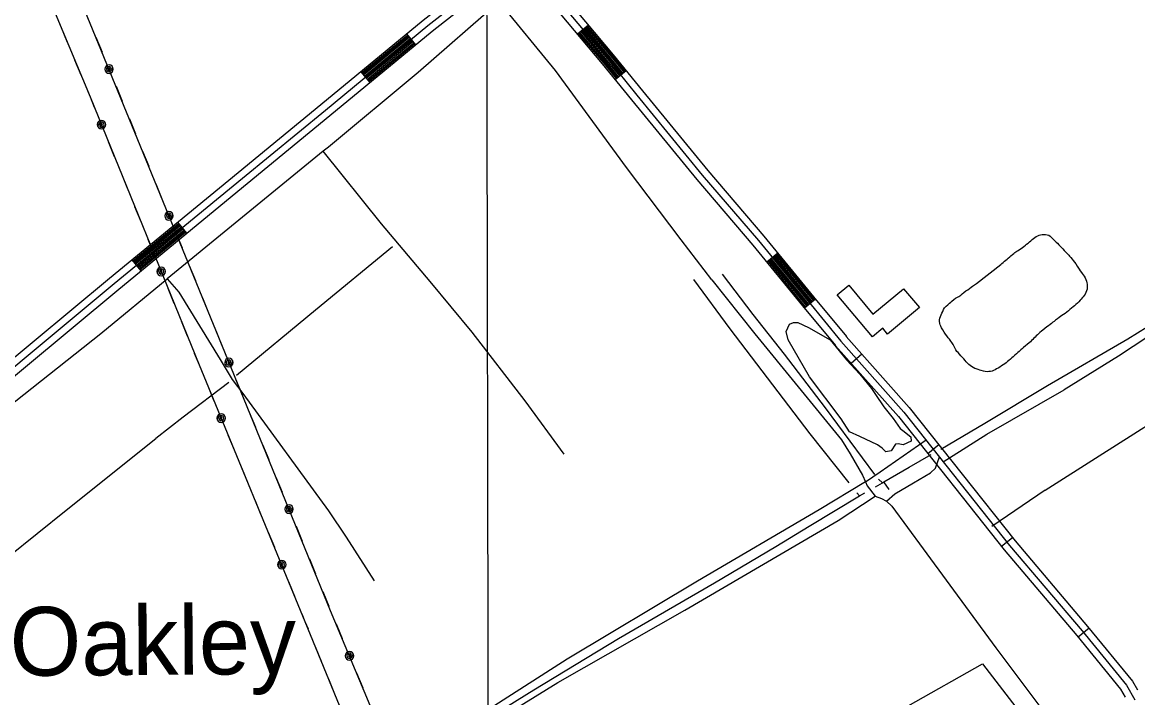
# Model space of a CAD drawing. Extents: x 3329332 to 3367211, y 631066 to 656469.
# Drawn here: x 3353510 to 3355862, y 642954 to 644377 of the extents above; entities that cross this region are included whole.
import ezdxf

# ---------------------------------------------------------------- set-up
doc = ezdxf.new("R2010")
doc.units = 0
for name, color, linetype in [('V-BLDG-OTLN', 7, 'Continuous'), ('V-DTCH-CNTR', 7, 'Continuous'), ('V-GRID-MAJR', 7, 'Continuous'), ('V-RIVR-JETY', 7, 'Continuous'), ('V-ROAD-CNTR', 7, 'Continuous'), ('V-TOPO-GNAM-IDEN', 7, 'Continuous'), ('V-TOPO-SHOR', 7, 'Continuous'), ('V-UTIL-LINE', 7, 'Continuous')]:
    doc.layers.add(name, color=color, linetype=linetype)

msp = doc.modelspace()

# ---------------------------------------------------------------- linework, layer by layer
at = {"layer": 'V-BLDG-OTLN'}
msp.add_lwpolyline([(3355401.4, 643776.5), (3355334.5, 643720.5), (3355324, 643733), (3355302.4, 643714.9), (3355228.3, 643803.3), (3355252.3, 643823.4), (3355303.4, 643762.3), (3355367.6, 643816)], close=True, dxfattribs=at)
at = {"layer": 'V-DTCH-CNTR'}
msp.add_line((3355666.5, 643391.5), (3355554.1, 643315), dxfattribs=at)
for points in [[(3354964.1, 643834.5), (3354899.2, 643919.1), (3354783.6, 644071.4), (3354633.9, 644275.9), (3354515.7, 644420.6), (3354344.4, 644271.6), (3354155.7, 644114.5), (3354144.7, 644105.6), (3353958.7, 643953.8), (3353815.2, 643837), (3353840.1, 643808.4)], [(3354369.6, 643831.2), (3354267, 643952.7), (3354144.7, 644105.6)], [(3353305.7, 643437.1), (3353458.6, 643550.1), (3353675.6, 643721.3), (3353815.2, 643837)], [(3354652.7, 643467.6), (3354570, 643579.4), (3354458.2, 643724.4), (3354369.6, 643831.2)], [(3354964.1, 643834.5), (3355054.2, 643721.2), (3355237.2, 643497.4), (3355255.3, 643468), (3355281.3, 643423.1), (3355287.7, 643408.8), (3355291.4, 643400.4), (3355308.1, 643379), (3355321.3, 643373.8), (3355332.2, 643368.6), (3355343.1, 643357.5), (3355409.2, 643267.8), (3355562.3, 643059.5), (3355676.2, 642907.2)], [(3353840.1, 643808.4), (3353927, 643666.5), (3353952.3, 643624.6), (3353974.8, 643595.1), (3354155.5, 643347.9), (3354192.5, 643292.8), (3354251.9, 643200.1)], [(3355666.5, 643391.5), (3355780.1, 643464.1), (3355970.6, 643584.8), (3356029.1, 643619), (3355942.8, 643754.1), (3355821.4, 643673.9), (3355706.4, 643602.9)], [(3355451.4, 643451.4), (3355543.4, 643509.3), (3355706.4, 643602.9)], [(3355287.7, 643408.8), (3355318.6, 643430.1), (3355415.4, 643497.3)], [(3355332.2, 643368.6), (3355349.9, 643383.9), (3355388.9, 643407), (3355424.9, 643428), (3355435.2, 643438.2), (3355443.8, 643461.8)], [(3355287.7, 643408.8), (3355190.3, 643350.2), (3354933.8, 643199.5), (3354658.7, 643035.1), (3354478.6, 642920.1), (3354273, 642789), (3354003.3, 642630.8), (3353935.2, 642590), (3353707.7, 642453.7)], [(3353957.6, 642557.2), (3354113.8, 642657), (3354391.3, 642832.9), (3354639.4, 642986), (3354906.7, 643138.9), (3355230.5, 643327.6), (3355308.1, 643379)]]:
    msp.add_lwpolyline(points, dxfattribs=at)
at = {"layer": 'V-GRID-MAJR'}
msp.add_spline([(3354505.6, 636487.8), (3354493.2, 642546.1), (3354480.9, 648607.4), (3354468.6, 654668.8), (3354468.6, 654671.8)], degree=3, dxfattribs=at)
at = {"layer": 'V-RIVR-JETY'}
msp.add_lwpolyline([(3355384, 643495), (3355367.5, 643487.2), (3355356.9, 643489.2), (3355351, 643488.5), (3355341.8, 643474.4), (3355330.4, 643472.1), (3355322.6, 643480.1), (3355312.9, 643486.8), (3355275.7, 643504.7), (3355254.1, 643514.7), (3355236.6, 643541.5), (3355169.6, 643630.4), (3355124.6, 643708), (3355120.8, 643726.1), (3355127.6, 643741.4), (3355136.2, 643744.9), (3355145.3, 643744.8), (3355167.6, 643734.5), (3355213, 643708.6), (3355247.7, 643666), (3355275.7, 643635.9), (3355300.7, 643605.9), (3355308.9, 643593.3), (3355326.4, 643566.8), (3355346.2, 643542.7), (3355360.6, 643521.4), (3355366.5, 643517.1), (3355383.7, 643503.6), (3355384, 643495)], dxfattribs=at)
at = {"layer": 'V-ROAD-CNTR'}
for p, q in [((3354703.5, 644371.5), (3354680.5, 644352.2)), ((3354320, 644352.9), (3354339.1, 644329.8)), ((3354783.5, 644275.1), (3354760.2, 644256.2)), ((3354223.6, 644273.3), (3354242.7, 644250.2)), ((3353837.3, 643956), (3353856.3, 643932.8)), ((3353740.7, 643876.7), (3353759.7, 643853.5)), ((3355103.1, 643890.8), (3355079.9, 643871.7)), ((3355182.4, 643794.1), (3355159.3, 643775.1)), ((3355280.3, 643678.2), (3355257.8, 643658.3)), ((3355442.5, 643487), (3355419, 643468.4)), ((3355597.8, 643291.2), (3355574.3, 643272.5)), ((3355759.2, 643100.6), (3355736, 643081.6))]:
    msp.add_line(p, q, dxfattribs=at)
for points in [[(3353218.9, 643449.7), (3353296.3, 643507.8), (3353694.1, 643838.5), (3353964.8, 644060.6), (3354139.5, 644203.9), (3354355.5, 644382.2), (3354528.4, 644517.8)], [(3353227.9, 643437.7), (3353305.6, 643496.1), (3353703.7, 643826.9), (3353974.3, 644049), (3354149, 644192.4), (3354364.9, 644370.5), (3354558, 644521.9), (3354744.4, 644299.4), (3354805.8, 644223.8), (3354943.7, 644055.6), (3355061.9, 643917.3), (3355166.7, 643789.7), (3355235.9, 643705.7)], [(3354577.3, 644522.2), (3354755.9, 644308.9), (3354817.4, 644233.3), (3354955.2, 644065.2), (3355073.4, 643927), (3355178.3, 643799.2), (3355247.4, 643715.2)], [(3353236.9, 643425.7), (3353314.9, 643484.3), (3353713.2, 643815.4), (3353983.8, 644037.4), (3354158.5, 644180.8), (3354374.3, 644358.8), (3354555.8, 644501.2), (3354732.8, 644289.9), (3354794.2, 644214.3), (3354932.2, 644046), (3355050.4, 643907.7), (3355155.1, 643780.1), (3355224.3, 643696.1)], [(3354701.2, 644369.6), (3354753.6, 644307), (3354781.1, 644273.2)], [(3354225.5, 644271), (3354321.9, 644350.6)], [(3354227.4, 644268.7), (3354323.8, 644348.3)], [(3354229.3, 644266.4), (3354325.7, 644346)], [(3354682.8, 644354.1), (3354735.1, 644291.8), (3354762.5, 644258)], [(3354685.1, 644356.1), (3354737.4, 644293.7), (3354764.8, 644259.9)], [(3354687.4, 644358), (3354739.7, 644295.6), (3354767.2, 644261.8)], [(3354689.7, 644359.9), (3354742, 644297.5), (3354769.5, 644263.7)], [(3354692, 644361.9), (3354744.4, 644299.4), (3354771.8, 644265.6)], [(3354694.3, 644363.8), (3354746.7, 644301.3), (3354774.1, 644267.5)], [(3354696.6, 644365.7), (3354749, 644303.2), (3354776.5, 644269.4)], [(3354698.9, 644367.6), (3354751.3, 644305.1), (3354778.8, 644271.3)], [(3354231.2, 644264.1), (3354327.7, 644343.6)], [(3354233.1, 644261.8), (3354329.6, 644341.3)], [(3354235.1, 644259.5), (3354331.5, 644339)], [(3354237, 644257.1), (3354333.4, 644336.7)], [(3354238.9, 644254.8), (3354335.3, 644334.4)], [(3354240.8, 644252.5), (3354337.2, 644332.1)], [(3353742.6, 643874.3), (3353839.2, 643953.6)], [(3353744.5, 643872), (3353841.1, 643951.3)], [(3353746.4, 643869.7), (3353843, 643949)], [(3353748.3, 643867.4), (3353844.9, 643946.7)], [(3353750.2, 643865.1), (3353846.8, 643944.4)], [(3353752.1, 643862.7), (3353848.7, 643942)], [(3353754, 643860.4), (3353850.6, 643939.7)], [(3353755.9, 643858.1), (3353852.5, 643937.4)], [(3353757.8, 643855.8), (3353854.4, 643935.1)], [(3355084.6, 643875.5), (3355159.7, 643784), (3355163.9, 643778.9)], [(3355086.9, 643877.4), (3355162, 643785.9), (3355166.2, 643780.8)], [(3355089.2, 643879.3), (3355164.3, 643787.8), (3355168.5, 643782.7)], [(3355091.5, 643881.2), (3355166.7, 643789.7), (3355170.8, 643784.6)], [(3355093.9, 643883.1), (3355169, 643791.6), (3355173.1, 643786.5)], [(3355096.2, 643885), (3355171.3, 643793.5), (3355175.5, 643788.4)], [(3355098.5, 643886.9), (3355173.6, 643795.4), (3355177.8, 643790.3)], [(3355100.8, 643888.9), (3355175.9, 643797.3), (3355180.1, 643792.2)], [(3355082.3, 643873.6), (3355157.4, 643782), (3355161.6, 643777)], [(3355247.1, 643715.6), (3355380.1, 643565.6), (3355603, 643284.6), (3355756.1, 643104.5), (3355850.4, 642989.3), (3355861.1, 642970.5)], [(3355224.6, 643695.7), (3355357.1, 643546.4), (3355579.9, 643265.5), (3355733, 643085.2), (3355825.6, 642972.2), (3355835.2, 642955.3)], [(3355235.9, 643705.7), (3355368.6, 643556), (3355591.4, 643275.1), (3355744.5, 643094.8), (3355838, 642980.7), (3355855.7, 642949.7)]]:
    msp.add_lwpolyline(points, dxfattribs=at)
at = {"layer": 'V-TOPO-SHOR'}
for p, q in [((3355315, 643415), (3355323.4, 643406.9)), ((3355337.8, 643392.6), (3355326.7, 643408.8)), ((3355269.3, 643385.6), (3355275.1, 643379.4))]:
    msp.add_line(p, q, dxfattribs=at)
for points in [[(3355573, 643866.8), (3355575.3, 643869), (3355577.7, 643871.4), (3355580.6, 643873.9), (3355583.5, 643876.4), (3355586.2, 643878.4), (3355588.8, 643880.4), (3355592.2, 643883.4), (3355594.5, 643885.6), (3355597.4, 643887.9), (3355600.2, 643890.3), (3355602.6, 643892.2), (3355606.8, 643895), (3355609.5, 643896.6), (3355612.8, 643898.7), (3355616, 643900.8), (3355618.5, 643902.9), (3355621.7, 643905.3), (3355624.8, 643907.5), (3355627.4, 643909.6), (3355630.5, 643912.3), (3355633.6, 643914.8), (3355636.4, 643917.1), (3355639.2, 643919.4), (3355642.3, 643922), (3355644.8, 643923.8), (3355647.8, 643925.8), (3355650.8, 643927.3), (3355653.7, 643928.5), (3355656.9, 643929.3), (3355660.4, 643929.9), (3355664.1, 643930.4), (3355667.4, 643930.4), (3355670.8, 643929.8), (3355674.4, 643928.6), (3355677.1, 643926.5), (3355679.7, 643924.1), (3355681.9, 643922), (3355685, 643919.1), (3355687.2, 643916.9), (3355689.7, 643914.4), (3355692.3, 643911.7), (3355695.3, 643908.6), (3355698.5, 643905.4), (3355700.7, 643903.2), (3355703.9, 643899.7), (3355706.9, 643896.4), (3355710.3, 643892.8), (3355712.8, 643890.3), (3355716.2, 643886.8), (3355718.2, 643884.4), (3355720.8, 643881.5), (3355723.5, 643878.3), (3355725.8, 643875.4), (3355728.4, 643871.7), (3355731, 643868.2), (3355733.8, 643863.8), (3355735.8, 643861.1), (3355738.3, 643857.5), (3355740.6, 643853.9), (3355743, 643850.4), (3355744.8, 643847.9), (3355746.8, 643845), (3355748.7, 643842.6), (3355750.9, 643838.8), (3355752.5, 643835.2), (3355753.7, 643831.8), (3355754.4, 643828.6), (3355755, 643825.4), (3355755.3, 643821.4), (3355755.2, 643818.3), (3355754.8, 643815.1), (3355753.5, 643811.2), (3355752.4, 643808.2), (3355750.7, 643804.7), (3355749, 643801.8), (3355746.8, 643798.8), (3355744.8, 643796.5), (3355742.7, 643794.3), (3355740.3, 643791.7), (3355737.7, 643788.7), (3355734.9, 643785.9), (3355731.4, 643782.6), (3355728.5, 643780.2), (3355725.6, 643777.9), (3355722.2, 643775), (3355718.6, 643772), (3355715.7, 643769.7), (3355712, 643766.8), (3355708.4, 643764), (3355705.4, 643761.8), (3355701.9, 643759.4), (3355698.6, 643757.2), (3355695.9, 643755.4), (3355692.4, 643752.8), (3355688.6, 643749.7), (3355685.3, 643747.1), (3355683, 643745.3), (3355679.8, 643742.8), (3355677.4, 643740.9), (3355673.3, 643737.8)], [(3354290.7, 643904.6), (3354128.3, 643770.8), (3353961.6, 643633.4)], [(3355503.2, 643814), (3355507.1, 643816.8), (3355510.8, 643819.6), (3355513.6, 643821.7), (3355517.3, 643824.4), (3355522.1, 643827.2), (3355573, 643866.8)], [(3355253.2, 643406.9), (3355170.8, 643510.4), (3355002.3, 643731.8), (3354926, 643835.2)], [(3354985.6, 643847), (3355050.5, 643762), (3355116.3, 643678.4), (3355202.5, 643565), (3355306.7, 643424.8)], [(3355673.3, 643737.8), (3355669.9, 643735.4), (3355665.8, 643732.1), (3355661.8, 643729), (3355658.8, 643726.6), (3355655.6, 643723.9), (3355652.9, 643721.7), (3355650.5, 643719.1), (3355647.8, 643716.4), (3355645.3, 643714), (3355643, 643711.7), (3355640.5, 643709.3), (3355637.7, 643706.8), (3355635.4, 643704.4), (3355632.6, 643701.9), (3355628.7, 643698.4), (3355625.1, 643695.3), (3355621.2, 643692), (3355618.6, 643689.8), (3355615.2, 643687), (3355611.9, 643684), (3355609.2, 643681.5), (3355605.9, 643678.6), (3355602.9, 643675.9), (3355599.1, 643672.6), (3355596.4, 643670.1), (3355593.5, 643667.8), (3355589.8, 643664.5), (3355587.3, 643662.4), (3355584.2, 643660), (3355581.3, 643657.7), (3355577.9, 643655.3), (3355574.5, 643653.2), (3355571, 643650.8), (3355567.7, 643648.9), (3355564.3, 643647.2), (3355560.9, 643645.1), (3355557.9, 643643.5), (3355554.8, 643642.3), (3355551.4, 643641.5), (3355547.7, 643641.4), (3355544.1, 643641), (3355540.2, 643641.4), (3355536.7, 643642.3), (3355531.7, 643643.7), (3355528.8, 643644.4), (3355525.1, 643645.7), (3355521.3, 643646.9), (3355518.2, 643648), (3355514.5, 643650), (3355511, 643652), (3355508.5, 643653.9), (3355505.8, 643656.4), (3355502.9, 643659.2), (3355500, 643661.9), (3355498, 643664.5), (3355494.9, 643668.2), (3355491.6, 643671.9), (3355489, 643674.6), (3355486, 643677.9), (3355482.9, 643681.3), (3355480.6, 643683.9), (3355478.5, 643687.1), (3355475.9, 643691.7), (3355473.8, 643695.7), (3355472.3, 643698.4), (3355469.9, 643702.5), (3355467.6, 643705.8), (3355464.8, 643709.4), (3355462.4, 643712.4), (3355459.5, 643716.5), (3355456.6, 643720.4), (3355453.6, 643724.7), (3355451, 643729.2), (3355448.3, 643733.9), (3355446.9, 643736.8), (3355445.3, 643740), (3355444.4, 643742.9), (3355443.7, 643747.5), (3355443.5, 643750.6), (3355444.2, 643753.7), (3355445.9, 643757.6), (3355447.4, 643761.3), (3355449, 643764.6), (3355450.5, 643768.3), (3355452.5, 643772.3), (3355454.6, 643775.8), (3355457.7, 643779), (3355461.3, 643782.2), (3355464.9, 643785.4), (3355467.5, 643787.8), (3355470.1, 643790), (3355473.7, 643793.1), (3355477.3, 643795.8), (3355480.5, 643797.6), (3355484.5, 643799.9), (3355488.6, 643802.6), (3355491.5, 643805), (3355495.1, 643807.9), (3355499.6, 643811.4), (3355503.2, 643814)], [(3355671.4, 643612.4), (3355841, 643710.4), (3355942.7, 643773.6)], [(3353945.5, 643618.2), (3353849.4, 643545.4), (3353791.3, 643500.7)], [(3355446.4, 643478.2), (3355539.7, 643532.4), (3355671.4, 643612.4)], [(3353414, 643199.1), (3353480, 643251.1), (3353602.6, 643349.1), (3353791.3, 643500.7)], [(3355308.6, 643398.3), (3355323.4, 643406.9), (3355326.7, 643408.8), (3355379.8, 643439.7), (3355426.5, 643466.9)], [(3353958.4, 642575.6), (3354053.3, 642635.2), (3354196.4, 642725), (3354396.3, 642851), (3354588.4, 642970.9), (3354766.7, 643078.7), (3354969.5, 643196.3), (3355098.9, 643273.1), (3355169.3, 643315.4), (3355275.1, 643379.4), (3355286.4, 643386.2)], [(3355249.6, 642854.4), (3355377.8, 642937), (3355534.5, 643025.7), (3355668.3, 642852.1)]]:
    msp.add_lwpolyline(points, dxfattribs=at)
at = {"layer": 'V-UTIL-LINE'}
for points in [[(3355057, 640957.9), (3354832.9, 641498.1), (3354614.4, 642039.4), (3354397.9, 642569), (3354160.1, 643137.5), (3353936.7, 643682.3), (3353706.1, 644246.6), (3353477.2, 644804.1), (3353249.1, 645361.4), (3353019.3, 645913.3), (3352822.6, 646394.7), (3352634.2, 646842.1), (3352469.8, 647270.3), (3352329.5, 647842.2)], [(3354997, 640934.2), (3354562.2, 642013.6), (3354336, 642554.4), (3354106.7, 643114.4), (3353883.4, 643654.7), (3353653.6, 644219.7), (3353419.4, 644779.3), (3353196.6, 645329.8), (3352962.2, 645897), (3352767.7, 646365.7), (3352563.9, 646828.2), (3352422, 647304), (3352297.4, 647805.2)], [(3353605.5, 644334.5), (3353592.4, 644365.9)], [(3353665.2, 644346.2), (3353678.1, 644314.8)], [(3353634.1, 644266.2), (3353621, 644297.6)], [(3353692.9, 644278.7), (3353694.5, 644281.1), (3353692.1, 644281), (3353690.7, 644278.7), (3353692.1, 644276.1), (3353695.3, 644277.3), (3353697.2, 644281.6), (3353694.1, 644284.5), (3353689.3, 644283.9), (3353687.3, 644279.8), (3353688.1, 644275.3), (3353692.3, 644273.1), (3353697.5, 644274.9), (3353701.2, 644282.1), (3353699.3, 644285.1), (3353696.4, 644287), (3353692.9, 644287.7), (3353689.5, 644287), (3353686.5, 644285.1), (3353684.6, 644282.2), (3353683.9, 644278.7), (3353684.6, 644275.3), (3353686.5, 644272.4), (3353689.4, 644270.4), (3353692.9, 644269.7), (3353696.3, 644270.4), (3353699.2, 644272.3), (3353701.2, 644275.2), (3353701.9, 644278.7), (3353701.2, 644282.1)], [(3353662.4, 644197.9), (3353653.6, 644219.7), (3353649.5, 644229.3)], [(3353707.7, 644242.6), (3353720.6, 644211.2)], [(3353677.1, 644161.8), (3353675.6, 644159.3), (3353677.9, 644159.4), (3353679.3, 644161.8), (3353677.9, 644164.3), (3353674.7, 644163.2), (3353672.8, 644158.9), (3353675.9, 644156), (3353680.7, 644156.6), (3353682.7, 644160.7), (3353682, 644165.1), (3353677.7, 644167.4), (3353672.5, 644165.6), (3353668.8, 644158.4), (3353670.7, 644155.4), (3353673.6, 644153.5), (3353677.1, 644152.8), (3353680.5, 644153.4), (3353683.5, 644155.4), (3353685.4, 644158.3), (3353686.1, 644161.7), (3353685.5, 644165.1), (3353683.5, 644168.1), (3353680.6, 644170.1), (3353677.2, 644170.8), (3353673.8, 644170.1), (3353670.8, 644168.2), (3353668.8, 644165.3), (3353668.1, 644161.8), (3353668.8, 644158.4)], [(3353735.7, 644174.1), (3353748.5, 644142.7)], [(3353704.6, 644094.1), (3353691.8, 644125.6)], [(3353763.7, 644105.6), (3353776.5, 644074.2)], [(3353732.5, 644025.6), (3353719.7, 644057.1)], [(3353791.7, 644037.1), (3353804.5, 644005.7)], [(3353760.4, 643957), (3353747.6, 643988.5)], [(3353819.3, 643969.6), (3353820.9, 643972), (3353818.5, 643971.9), (3353817.1, 643969.5), (3353818.5, 643967), (3353821.7, 643968.1), (3353823.6, 643972.4), (3353820.5, 643975.3), (3353815.7, 643974.7), (3353813.7, 643970.6), (3353814.4, 643966.2), (3353818.7, 643963.9), (3353823.9, 643965.7), (3353827.6, 643973), (3353825.7, 643975.9), (3353822.8, 643977.9), (3353819.3, 643978.6), (3353815.9, 643977.9), (3353813, 643975.9), (3353811, 643973), (3353810.3, 643969.6), (3353811, 643966.1), (3353812.9, 643963.2), (3353815.8, 643961.3), (3353819.2, 643960.6), (3353822.7, 643961.2), (3353825.6, 643963.2), (3353827.6, 643966.1), (3353828.3, 643969.5), (3353827.6, 643973)], [(3353834, 643933.5), (3353846.9, 643902)], [(3353788.3, 643888.5), (3353775.5, 643920)], [(3353803, 643852.4), (3353801.4, 643850), (3353803.7, 643850), (3353805.2, 643852.4), (3353803.8, 643854.9), (3353800.6, 643853.8), (3353798.7, 643849.5), (3353801.8, 643846.6), (3353806.6, 643847.2), (3353808.6, 643851.3), (3353807.8, 643855.7), (3353803.6, 643858), (3353798.4, 643856.2), (3353794.6, 643849), (3353796.6, 643846.1), (3353799.5, 643844.1), (3353802.9, 643843.4), (3353806.4, 643844), (3353809.3, 643846), (3353811.3, 643848.9), (3353812, 643852.3), (3353811.3, 643855.8), (3353809.4, 643858.7), (3353806.5, 643860.7), (3353803, 643861.4), (3353799.6, 643860.7), (3353796.7, 643858.8), (3353794.7, 643855.9), (3353794, 643852.4), (3353794.6, 643849)], [(3353862, 643865), (3353874.9, 643833.5)], [(3353830.5, 643784.8), (3353817.7, 643816.2)], [(3353890, 643796.5), (3353902.9, 643765)], [(3353858.4, 643716.2), (3353845.6, 643747.7)], [(3353918, 643728), (3353930.9, 643696.5)], [(3353886.3, 643647.7), (3353883.4, 643654.7), (3353873.4, 643679.2)], [(3353945.7, 643660.4), (3353947.2, 643662.8), (3353944.9, 643662.7), (3353943.5, 643660.4), (3353944.9, 643657.8), (3353948.1, 643658.9), (3353950, 643663.2), (3353946.9, 643666.1), (3353942, 643665.6), (3353940.1, 643661.4), (3353940.8, 643657), (3353945.1, 643654.8), (3353950.3, 643656.5), (3353954, 643663.8), (3353952.1, 643666.7), (3353949.1, 643668.7), (3353945.7, 643669.4), (3353942.2, 643668.7), (3353939.3, 643666.8), (3353937.4, 643663.9), (3353936.7, 643660.4), (3353937.3, 643657), (3353939.3, 643654), (3353942.2, 643652.1), (3353945.6, 643651.4), (3353949.1, 643652.1), (3353952, 643654), (3353954, 643656.9), (3353954.7, 643660.4), (3353954, 643663.8)], [(3353960.5, 643624.3), (3353973.4, 643592.8)], [(3353914.6, 643579.3), (3353901.6, 643610.7)], [(3353929.4, 643543.2), (3353927.9, 643540.8), (3353930.2, 643540.9), (3353931.6, 643543.3), (3353930.2, 643545.8), (3353927, 643544.7), (3353925.1, 643540.4), (3353928.3, 643537.5), (3353933.1, 643538.1), (3353935, 643542.2), (3353934.3, 643546.6), (3353930, 643548.9), (3353924.8, 643547.1), (3353921.1, 643539.8), (3353923.1, 643536.9), (3353926, 643534.9), (3353929.4, 643534.2), (3353932.9, 643534.9), (3353935.8, 643536.9), (3353937.8, 643539.8), (3353938.4, 643543.2), (3353937.8, 643546.7), (3353935.8, 643549.6), (3353932.9, 643551.6), (3353929.5, 643552.2), (3353926, 643551.6), (3353923.1, 643549.6), (3353921.1, 643546.7), (3353920.4, 643543.3), (3353921.1, 643539.8)], [(3353988.5, 643555.8), (3354001.4, 643524.4)], [(3353957.3, 643475.8), (3353944.3, 643507.2)], [(3354016.6, 643487.4), (3354029.5, 643455.9)], [(3353985.6, 643407.4), (3353972.6, 643438.8)], [(3354044.7, 643418.9), (3354057.6, 643387.4)], [(3354013.8, 643339), (3354000.9, 643370.4)], [(3354072.4, 643351.4), (3354074, 643353.8), (3354071.6, 643353.7), (3354070.2, 643351.4), (3354071.6, 643348.8), (3354074.8, 643349.9), (3354076.7, 643354.2), (3354073.6, 643357.1), (3354068.8, 643356.5), (3354066.8, 643352.4), (3354067.6, 643348), (3354071.8, 643345.7), (3354077, 643347.5), (3354080.7, 643354.8), (3354078.8, 643357.7), (3354075.9, 643359.7), (3354072.4, 643360.4), (3354069, 643359.7), (3354066.1, 643357.8), (3354064.1, 643354.8), (3354063.4, 643351.4), (3354064.1, 643347.9), (3354066, 643345), (3354068.9, 643343.1), (3354072.4, 643342.4), (3354075.8, 643343), (3354078.7, 643345), (3354080.7, 643347.9), (3354081.4, 643351.3), (3354080.7, 643354.8)], [(3354087.2, 643315.3), (3354100.1, 643283.8)], [(3354042.1, 643270.6), (3354029.1, 643302)], [(3354057, 643234.6), (3354055.4, 643232.1), (3354057.8, 643232.2), (3354059.2, 643234.6), (3354057.8, 643237.1), (3354054.6, 643236), (3354052.7, 643231.7), (3354055.8, 643228.8), (3354060.6, 643229.4), (3354062.6, 643233.5), (3354061.8, 643237.9), (3354057.6, 643240.2), (3354052.4, 643238.4), (3354048.7, 643231.1), (3354050.6, 643228.2), (3354053.6, 643226.2), (3354057, 643225.6), (3354060.4, 643226.2), (3354063.4, 643228.2), (3354065.3, 643231.1), (3354066, 643234.6), (3354065.3, 643238), (3354063.4, 643240.9), (3354060.5, 643242.9), (3354057, 643243.6), (3354053.6, 643242.9), (3354050.6, 643240.9), (3354048.7, 643238), (3354048, 643234.6), (3354048.7, 643231.1)], [(3354115.3, 643246.8), (3354128.2, 643215.4)], [(3354084.9, 643167.1), (3354071.9, 643198.5)], [(3354143.3, 643178.3), (3354156.2, 643146.9)], [(3354113.1, 643098.7), (3354106.7, 643114.4), (3354100.2, 643130.1)], [(3354171.6, 643110), (3354184.7, 643078.6)], [(3354141.1, 643030.2), (3354128.3, 643061.7)], [(3354199.8, 643042.6), (3354201.3, 643045), (3354199, 643044.9), (3354197.6, 643042.6), (3354199, 643040), (3354202.2, 643041.2), (3354204.1, 643045.5), (3354201, 643048.4), (3354196.1, 643047.8), (3354194.2, 643043.6), (3354195, 643039.2), (3354199.2, 643037), (3354204.4, 643038.8), (3354208.1, 643046.1), (3354206.1, 643049), (3354203.2, 643050.9), (3354199.8, 643051.6), (3354196.3, 643050.9), (3354193.4, 643049), (3354191.5, 643046), (3354190.8, 643042.6), (3354191.5, 643039.1), (3354193.4, 643036.2), (3354196.4, 643034.3), (3354199.8, 643033.6), (3354203.3, 643034.3), (3354206.2, 643036.3), (3354208.1, 643039.2), (3354208.8, 643042.6), (3354208.1, 643046.1)], [(3354214.8, 643006.6), (3354228, 642975.3)], [(3354169.2, 642961.7), (3354156.3, 642993.2)]]:
    msp.add_lwpolyline(points, dxfattribs=at)

# ---------------------------------------------------------------- texts
at = {"layer": 'V-TOPO-GNAM-IDEN'}
msp.add_text('Oakley', height=145, rotation=0.3915, dxfattribs=at).set_placement((3353484, 643000.1))

doc.saveas('drawing.dxf')
